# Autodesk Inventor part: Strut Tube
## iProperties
Shininess: 64.0
Length Units: 11272
Angle Units: 11279
Time Units: 11290
Mass Units: 11283
Length Display Precision: 3
Angle Display Precision: 2
Compacted: True
Part Number: Strut Tube
Document SubType Name: Modeling
Created: 2005-03
Designer: Admin
Manufacturer: Standard
Standards Organization: Custom
Density: 1 g/cm^3
Density: 0.0
Volumn: 0.0
Area: 0.0
PropertySet Name: Model Information
Control State: 0
Master: False
Checked Out: False
Author: Admin
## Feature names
1. ExtrusionBlind1
2. Hole1
3. RevolutionFull1
4. Fillet1
